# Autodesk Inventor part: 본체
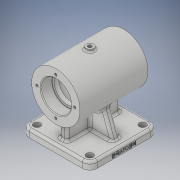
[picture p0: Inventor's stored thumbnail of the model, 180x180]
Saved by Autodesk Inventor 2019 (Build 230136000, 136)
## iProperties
Created: 2019-06
Part Number: 본체
Material: 알루미늄 6061
Document SubType Name: Modeling
Designer: SCD-A08
Density: 2.7 g/cm^3
Appearance: 알루미늄 - 평지
Mass: 228.506 g
Surface Area: 626.551 cm^2
Volume: 228.506 cm^3
Author: SCD-A08
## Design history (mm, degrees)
sketch "스케치1"
  geometry: L1 (0, 45)-(0, -45); L2 (32, 45)-(20, 45); L3 (20, -45)-(32, -45); L4 (32, -45)-(32, 45); L5 (19.7, 30)-(17, 30); L6 (17, 30)-(17, 24); L7 (17, 24)-(22, 24); L8 (32, 26.413)-(32, 33.764); L9 (22, -24)-(17, -24); L10 (17, -24)-(17, -30); L11 (17, -30)-(19.7, -30); L12 (32, -29.318)-(32, -19.232); L13 (25, 21)-(25, -21); L14 (32, -19.232)-(32, 26.413); L15 (20, 45)-(20, 30.3); L16 (20, -30.3)-(20, -45); A1 r 3 centre (22, 21) between (25, 21) and (22, 24); A2 r 3 centre (22, -21) between (22, -24) and (25, -21); A3 r 0.3 centre (19.7, -30.3) between (20, -30.3) and (19.7, -30); A4 r 0.3 centre (19.7, 30.3) between (19.7, 30) and (20, 30.3); 6 further points
  constraints: 32 end point, 11 point on line, 8 parallel, 8 point on circle, 8 tangent, 4 centre point, 4 perpendicular, 3 horizontal, 2 equal radius, 2 horizontal alignment, 1 coincident, 1 midpoint, 1 vertical
  dimensions: "d0" = 90 distance of L1.start L1.end; "d2" = 64 diameter of L4 L1; "d3" = 40 diameter of L15 L1; "d4" = 34 diameter of L6 L1; "d5" = 40 diameter of L16 L1; "d6" = 50 diameter of L13 L1; "d7" = 90 distance of L3.end L2.start; "d8" = 15 distance of L2.end point (20, 30); "d9" = 15 distance of point (20, -30) L3.start; "d10" = 48 distance of point (25, 24) point (25, -24); "d11" = 6 distance of L9.end L10.end; "d12" = 3 radius of A1; "d13" = 0.3 radius of A3
revolve "회전1" sketch "스케치1" stored, may be unused: angle "d14" = 90 deg
node "작업 평면1"
sketch "스케치2"
  geometry: L1 (35, 45)-(-35, 45); L2 (-45, 35)-(-45, -35); L3 (-35, -45)-(35, -45); L4 (45, -35)-(45, 35); L5 (45, 45)-(-45, -45); L6 (-45, 45)-(45, -45); C1 r 4.5 at (35, 35); C2 r 4.5 at (-35, 35); C3 r 4.5 at (-35, -35); C4 r 4.5 at (35, -35); A1 r 10 centre (35, 35) between (45, 35) and (35, 45); A2 r 10 centre (35, -35) between (35, -45) and (45, -35); A3 r 10 centre (-35, -35) between (-45, -35) and (-35, -45); A4 r 10 centre (-35, 35) between (-35, 45) and (-45, 35); 1 further point
  constraints: 12 end point, 8 centre point, 8 point on circle, 8 point on line, 8 tangent, 4 coincident, 3 equal radius, 2 midpoint, 2 parallel, 1 horizontal, 1 perpendicular
  dimensions: "d16" = 90 distance of L6.end L5.end; "d17" = 90 distance of L5.end L6.start; "d18" = 10 radius of A1; "d19" = 9 diameter of C1; "d20" = 9 diameter of C2; "d21" = 9 diameter of C3; "d22" = 9 diameter of C4
extrude "돌출1" join sketch "스케치2" distance "d23" = 10; taper "d24" = 0 deg
sketch "스케치3"
  geometry: L1 (-5, 35)-(5, 35); L2 (5, 35)-(5, -35); L3 (5, -35)-(-5, -35); L4 (-5, -35)-(-5, 35); L5 (-5, 35)-(5, -35); L6 (5, 35)-(-5, -35); 1 further point
  constraints: 12 end point, 2 midpoint, 2 parallel, 1 horizontal, 1 perpendicular
  dimensions: "d25" = 10 distance of L2.end L3.end; "d26" = 70 distance of L1.end L2.end
extrude "돌출2" join sketch "스케치3" stored distance "d27" = 10; taper "d28" = 0 deg
sketch "스케치5"
  geometry: C1 r 2 at (0, 25); 1 further point
  constraints: 1 centre point, 1 vertical alignment
  dimensions: "d35" = 4 diameter of C1; "d36" = 25 distance of point (0, 0) C1.centre
hole "구멍1" sketch "스케치5" at (0, 25) diameter "d37" = 3.242; stored, may be unused: countersink angle "d41" = 90 deg, drill point angle "d43" = 118 deg; dims "d38" = 7, "d39" = 4, "d40" = 2, "d42" = 9
sketch "스케치7"
  geometry: L1 (-22, 40)-(22, 40); L2 (40, 22)-(40, -22); L3 (22, -40)-(-22, -40); L4 (-40, -22)-(-40, 22); L5 (-40, 40)-(40, -40); L6 (40, 40)-(-40, -40); L7 (-35, 25)-(-37, 25); L8 (-25, 35)-(-25, 37); L9 (-25, -35)-(-25, -37); L10 (-35, -25)-(-37, -25); L11 (35, -25)-(37, -25); L12 (25, -35)-(25, -37); L13 (25, 35)-(25, 37); L14 (35, 25)-(37, 25); A1 r 10 centre (-35, 35) between (-35, 45) and (-45, 35) reference; A2 r 10 centre (-35, 35) between (-35, 25) and (-25, 35); A3 r 3 centre (-37, 22) between (-37, 25) and (-40, 22); A4 r 3 centre (-22, 37) between (-22, 40) and (-25, 37); A5 r 3 centre (-22, -37) between (-25, -37) and (-22, -40); A6 r 10 centre (-35, -35) between (-25, -35) and (-35, -25); A7 r 3 centre (-37, -22) between (-40, -22) and (-37, -25); A8 r 3 centre (37, -22) between (37, -25) and (40, -22); A9 r 10 centre (35, -35) between (35, -25) and (25, -35); A10 r 3 centre (22, -37) between (22, -40) and (25, -37); A11 r 3 centre (22, 37) between (25, 37) and (22, 40); A12 r 10 centre (35, 35) between (25, 35) and (35, 25); A13 r 3 centre (37, 22) between (40, 22) and (37, 25); 1 further point
  constraints: 28 end point, 24 point on circle, 12 centre point, 6 tangent, 2 horizontal, 2 midpoint, 2 parallel, 2 perpendicular, 2 point on line, 1 coincident, 1 equal radius, 57 other
  dimensions: "d49" = 20 diameter of A2; "d50" = 3 radius of A3 (derived); "d53" = 360 deg dimension on point (0, 0) L7.end (derived); "d55" = 80 distance between parallel lines of L2 L4
extrude "돌출4" cut sketch "스케치7" distance "d56" = 5; taper "d57" = 0 deg
node "작업 평면2"
sketch "스케치8"
  geometry: C1 r 5 at (0, 0); 1 further point
  constraints: 1 centre point, 1 coincident
  dimensions: "d67" = 10 diameter of C1
extrude "돌출5" join sketch "스케치8" stored distance "d68" = 5; taper "d69" = 0 deg
sketch "스케치9"
  geometry: C1 r 5 at (0, 0) reference; 2 further points
  constraints: 1 coincident
hole "구멍2" sketch "스케치9" at (0, 0) diameter "d70" = 4.917; stored, may be unused: countersink angle "d74" = 90 deg, drill point angle "d76" = 118 deg; dims "d71" = 12, "d72" = 4, "d73" = 2, "d75" = 17.1
fillet "모깎기1" dims "d61" = 3, "d62" = 3, "d82" = 2
chamfer "모따기1" distance "d63" = 1; stored, may be unused: second distance "d64" = 2, angle "d65" = 45 deg
node "작업 평면3"
sketch "스케치10"
  geometry: L1 (-65, -35)-(-65, 35) reference; L2 (-65, 45)-(-58, 45) reference; 2 further points
  constraints: 1 other
  dimensions: "d78" = 4 distance from line of L1 point (-61, 0); "d79" = 45 distance from line of L2 point (-61, 0)
feature "엠보싱1" sketch "스케치10" dims "d0" = 90, "d2" = 64, "d3" = 40, "d4" = 34, "d5" = 40, "d6" = 50, "d7" = 90, "d8" = 15, "d9" = 15, "d10" = 48, "d11" = 6, "d12" = 3, "d13" = 0.3, "d80" = 0.5, "d81" = 0
sketch "스케치11"
  geometry: L1 (-45, -65)-(-45, -58) reference; L2 (-35, -65)-(-35, -55); L3 (-39.5, -55)-(-30.5, -55) reference; L4 (-35, -55)-(-23.058, -22.189); L5 (-35, -55)-(17.931, -55); L6 (0, 0)-(0, -73.154); L7 (35, -55)-(23.058, -22.189); L8 (35, -55)-(-35, -55) reference; L9 (35, -55)-(-35, -55); A1 r 32 centre (0, 0) between (-23.058, -22.189) and (23.058, -22.189); 1 further point
  constraints: 12 end point, 2 horizontal, 2 point on circle, 2 symmetric about line, 1 centre point, 1 coincident, 1 midpoint, 1 parallel, 1 vertical
  dimensions: "d83" = 10 distance between parallel lines of L1 L2; "d84" = 70 deg angle of L5 L4; "d85" = 64 diameter of A1
extrude "돌출6" join sketch "스케치11" stored distance "d86" = 10; taper "d87" = 0 deg
fillet "모깎기2" dims "d88" = 3
node "솔리드1"
pattern_circular "원형 패턴1" dims angle "d59" = 360 deg
mirror "미러1"
other parameters: "d15" = -65, "d66" = 35
